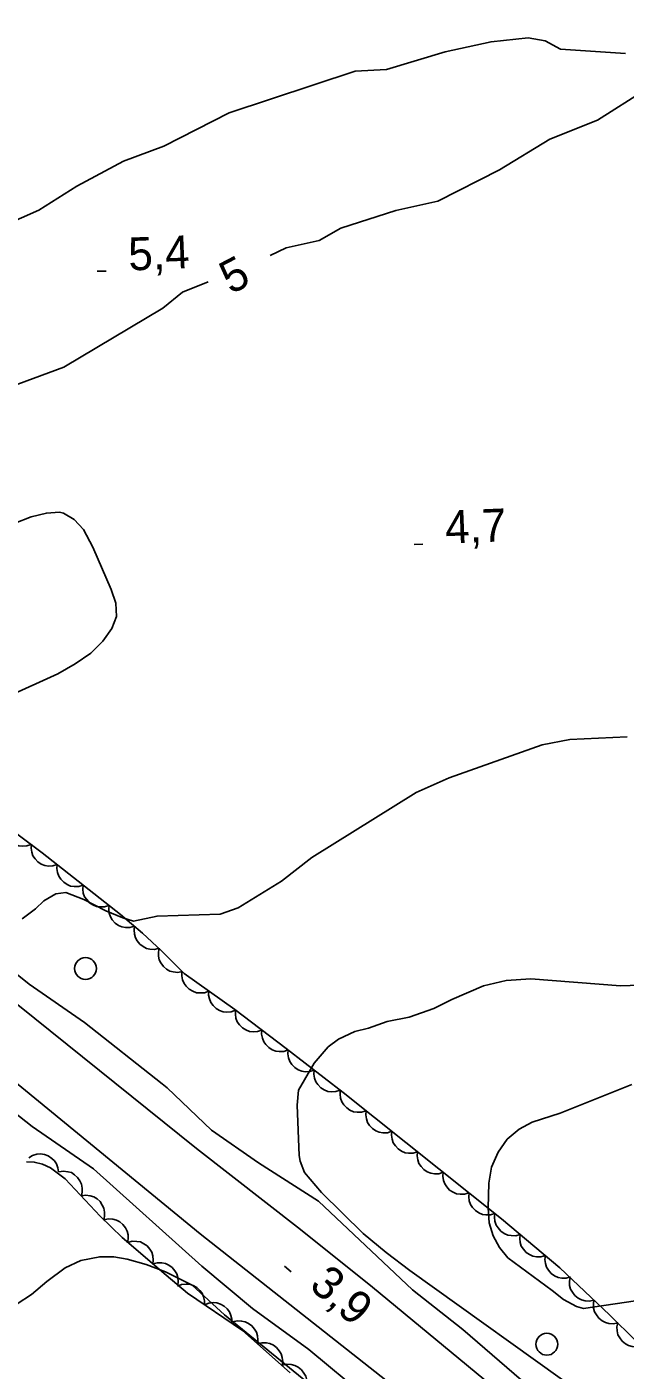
# Model space of a CAD drawing. Extents: x 336540 to 340074, y 5572036 to 5573747.
# Drawn here: x 337681.5 to 337736, y 5572772.1 to 5572894.5 of the extents above; entities that cross this region are included whole.
import ezdxf

# ---------------------------------------------------------------- set-up
doc = ezdxf.new("R2010")
doc.units = 0
for name, color, linetype in [('Niveau 1', 7, 'Continuous'), ('Niveau 19', 7, 'Continuous'), ('Niveau 2', 7, 'Continuous'), ('Niveau 3', 7, 'Continuous'), ('Niveau 36', 7, 'Continuous'), ('Niveau 4', 7, 'Continuous'), ('Niveau 44', 7, 'Continuous')]:
    doc.layers.add(name, color=color, linetype=linetype)

msp = doc.modelspace()

# ---------------------------------------------------------------- linework, layer by layer
at = {"layer": 'Niveau 1'}
for points in [[(337675.98, 5572874.9), (337682.62, 5572877.81), (337686.06, 5572880.01), (337690.32, 5572882.28), (337693.99, 5572883.65), (337699.93, 5572886.67), (337711.41, 5572890.48), (337714.27, 5572890.62), (337719.61, 5572892.25), (337723.79, 5572893.15), (337727.15, 5572893.51), (337728.7, 5572893.24), (337730.1, 5572892.47), (337736.03, 5572892.08)], [(337737.88, 5572888.79), (337733.47, 5572886), (337729.15, 5572884.28), (337724.56, 5572881.49), (337718.95, 5572878.64), (337715.11, 5572877.78), (337710.11, 5572876.16), (337708.12, 5572875.04), (337705.13, 5572874.37), (337703.68, 5572873.67)], [(337698.04, 5572871.27), (337695.7, 5572870.33), (337693.9, 5572868.87), (337684.87, 5572863.51), (337677.88, 5572860.94)], [(337736.92, 5572778.46), (337732.2, 5572777.75), (337731.56, 5572777.93), (337730.37, 5572778.57), (337729.36, 5572779.4), (337725.32, 5572782.38), (337724.55, 5572783.31), (337723.98, 5572784.38), (337723.61, 5572785.56), (337723.53, 5572786.92), (337723.58, 5572789.18), (337723.82, 5572790.62), (337724.43, 5572792), (337725.26, 5572793.17), (337726.33, 5572794.09), (337727.52, 5572794.72), (337730.09, 5572795.55), (337736.61, 5572798.15)]]:
    msp.add_lwpolyline(points, dxfattribs=at)
at = {"layer": 'Niveau 19'}
for points in [[(337747.9, 5572743.42), (337733.2, 5572755.24), (337714.79, 5572770.78), (337697.31, 5572784.55), (337659.54, 5572815.53), (337637.6, 5572833.7), (337630.44, 5572839.48), (337615.68, 5572851.12), (337606.88, 5572858.17), (337562.43, 5572894.51)], [(337585.33, 5572882.89), (337594.24, 5572875.34), (337602.7, 5572868.36), (337610.46, 5572862.12), (337627.18, 5572849.32), (337671.83, 5572812.51), (337696.95, 5572792.34), (337706.42, 5572784.95), (337712.98, 5572779.69), (337742.53, 5572755.28)]]:
    msp.add_lwpolyline(points, dxfattribs=at)
at = {"layer": 'Niveau 2'}
for points in [[(337680.35, 5572849.26), (337681.92, 5572849.87), (337683.3, 5572850.22), (337684.48, 5572850.29), (337684.84, 5572850.22), (337685.82, 5572849.63), (337686.67, 5572848.71), (337687.54, 5572847.12), (337689.19, 5572843.24), (337689.61, 5572842.01), (337689.67, 5572840.78), (337689.26, 5572839.71), (337688.45, 5572838.56), (337687.35, 5572837.46), (337685.91, 5572836.47), (337684.35, 5572835.57), (337679.73, 5572833.49)], [(337681.08, 5572813.24), (337682.32, 5572814.15), (337683.06, 5572814.88), (337684.17, 5572815.54), (337685.07, 5572815.64), (337686.71, 5572815), (337688.7, 5572813.99), (337690.27, 5572813.33), (337691.23, 5572813.05), (337693.38, 5572813.5), (337699.11, 5572813.68), (337700.75, 5572814.26), (337704.71, 5572816.68), (337707.46, 5572818.85), (337716.97, 5572824.77), (337719.96, 5572826.11), (337728.43, 5572829.1), (337730.95, 5572829.58), (337736.17, 5572829.84)], [(337740.01, 5572807.29), (337735.56, 5572807.14), (337727.39, 5572807.8), (337725.17, 5572807.65), (337723.09, 5572807.15), (337720.2, 5572805.9), (337718.57, 5572805.07), (337716.33, 5572804.3), (337714.32, 5572803.89), (337712.63, 5572803.29), (337711.39, 5572802.98), (337709.9, 5572802.3), (337708.95, 5572801.58), (337707.67, 5572800.11), (337706.26, 5572797.64), (337706.12, 5572796.27), (337706.3, 5572791.69), (337706.39, 5572791.17), (337706.81, 5572790.15), (337708.36, 5572788.31), (337712.14, 5572784.59), (337714.23, 5572782.86), (337716.39, 5572781.22), (337732.33, 5572769.81)], [(337707.41, 5572770.74), (337699.51, 5572777.17), (337696.57, 5572779.87), (337694.13, 5572781.09), (337692.39, 5572781.76), (337690.66, 5572782.24), (337689.44, 5572782.46), (337688.15, 5572782.47), (337686.44, 5572782.12), (337685.01, 5572781.45), (337683.35, 5572780.21), (337681.95, 5572779.03), (337680.64, 5572778.19)]]:
    msp.add_lwpolyline(points, dxfattribs=at)
at = {"layer": 'Niveau 3'}
for p, q in [((337687.93, 5572872.24), (337688.73, 5572872.26)), ((337716.77, 5572847.36), (337717.58, 5572847.39)), ((337704.98, 5572781.6), (337705.59, 5572781.08))]:
    msp.add_line(p, q, dxfattribs=at)
at = {"layer": 'Niveau 36'}
for centre in [(337686.86, 5572808.73), (337728.86, 5572774.5)]:
    msp.add_circle(centre, 1, dxfattribs=at)
at = {"layer": 'Niveau 4'}
for points in [[(337581.38, 5572889.43), (337592.52, 5572879.92), (337597.05, 5572876.33), (337601.9, 5572872.72), (337604.6, 5572870.54), (337609.27, 5572866.45), (337613.37, 5572862.68), (337615.91, 5572860.57), (337624.81, 5572853.45), (337633.16, 5572846.53), (337638.87, 5572842.03), (337643.3, 5572838.72), (337649.78, 5572834.11), (337653.45, 5572831.32), (337655.58, 5572829.56), (337666.32, 5572820.01), (337674.23, 5572813.3), (337681.73, 5572807.3), (337686.77, 5572803.82), (337693.83, 5572798.21)], [(337587.92, 5572869.67), (337590.52, 5572867.82), (337595.97, 5572864.2), (337609.79, 5572853.86), (337616.42, 5572848.76), (337622.03, 5572843.92), (337633.87, 5572834.25), (337644.17, 5572825.44), (337649.15, 5572820.98), (337662.3, 5572809.95), (337669.6, 5572804.24), (337675.77, 5572799.23), (337681.99, 5572794.33), (337687.59, 5572790.49), (337697.46, 5572781.61), (337702.07, 5572777.76), (337707.2, 5572774.01), (337712.37, 5572769.72), (337716.28, 5572765.83), (337730.4, 5572754.32), (337734.94, 5572750.56), (337739.53, 5572746.61)], [(337693.83, 5572798.21), (337694.3, 5572797.86), (337698.32, 5572794), (337702.62, 5572791.02), (337708.08, 5572787.53), (337716.63, 5572779.47), (337721.2, 5572775.84), (337729.89, 5572768.34), (337739.09, 5572761.24)]]:
    msp.add_lwpolyline(points, dxfattribs=at)
at = {"layer": 'Niveau 44'}
for points in [[(337681.91, 5572820.02), (337681.51, 5572819.89), (337681.11, 5572819.87), (337680.78, 5572819.9), (337680.45, 5572820.03), (337680.14, 5572820.22), (337679.87, 5572820.5), (337679.67, 5572820.76), (337679.55, 5572821.09), (337679.48, 5572821.45), (337679.5, 5572821.81)], [(337739.35, 5572772.45), (337734.57, 5572777.18), (337730.04, 5572781.47), (337724.74, 5572785.92), (337710.33, 5572797.42), (337705.12, 5572801.45), (337700.44, 5572804.98), (337695.84, 5572808.27), (337693.79, 5572810.35), (337692.04, 5572811.95), (337690.03, 5572813.64), (337682.91, 5572819.28), (337680.35, 5572821.18)], [(337684.28, 5572818.19), (337683.88, 5572818.07), (337683.48, 5572818.06), (337683.15, 5572818.1), (337682.83, 5572818.24), (337682.52, 5572818.45), (337682.26, 5572818.73), (337682.07, 5572819), (337681.96, 5572819.33), (337681.9, 5572819.7), (337681.93, 5572820.06)], [(337686.63, 5572816.33), (337686.24, 5572816.2), (337685.83, 5572816.2), (337685.5, 5572816.24), (337685.18, 5572816.38), (337684.87, 5572816.58), (337684.61, 5572816.87), (337684.42, 5572817.13), (337684.31, 5572817.47), (337684.26, 5572817.83), (337684.28, 5572818.19)], [(337688.99, 5572814.47), (337688.59, 5572814.34), (337688.18, 5572814.34), (337687.85, 5572814.38), (337687.53, 5572814.52), (337687.22, 5572814.72), (337686.97, 5572815.01), (337686.77, 5572815.27), (337686.66, 5572815.6), (337686.61, 5572815.97), (337686.63, 5572816.33)], [(337691.31, 5572812.57), (337690.9, 5572812.45), (337690.5, 5572812.46), (337690.17, 5572812.51), (337689.85, 5572812.66), (337689.55, 5572812.87), (337689.3, 5572813.16), (337689.12, 5572813.43), (337689.02, 5572813.77), (337688.97, 5572814.14), (337689.01, 5572814.5)], [(337693.55, 5572810.57), (337693.14, 5572810.47), (337692.73, 5572810.5), (337692.41, 5572810.56), (337692.1, 5572810.73), (337691.81, 5572810.95), (337691.57, 5572811.25), (337691.4, 5572811.53), (337691.31, 5572811.87), (337691.28, 5572812.24), (337691.33, 5572812.6)], [(337695.66, 5572808.45), (337695.25, 5572808.37), (337694.85, 5572808.42), (337694.53, 5572808.5), (337694.23, 5572808.68), (337693.95, 5572808.92), (337693.73, 5572809.23), (337693.57, 5572809.52), (337693.5, 5572809.86), (337693.49, 5572810.23), (337693.56, 5572810.58)], [(337698.08, 5572806.67), (337697.69, 5572806.52), (337697.28, 5572806.5), (337696.95, 5572806.52), (337696.62, 5572806.65), (337696.3, 5572806.84), (337696.03, 5572807.11), (337695.83, 5572807.36), (337695.7, 5572807.69), (337695.63, 5572808.06), (337695.64, 5572808.42)], [(337700.52, 5572804.93), (337700.13, 5572804.78), (337699.72, 5572804.76), (337699.39, 5572804.78), (337699.06, 5572804.9), (337698.74, 5572805.09), (337698.47, 5572805.36), (337698.27, 5572805.62), (337698.14, 5572805.95), (337698.07, 5572806.31), (337698.08, 5572806.67)], [(337702.91, 5572803.12), (337702.52, 5572802.98), (337702.11, 5572802.97), (337701.78, 5572803), (337701.45, 5572803.13), (337701.14, 5572803.33), (337700.88, 5572803.61), (337700.68, 5572803.87), (337700.56, 5572804.2), (337700.5, 5572804.56), (337700.52, 5572804.92)], [(337705.31, 5572801.31), (337704.91, 5572801.17), (337704.5, 5572801.16), (337704.18, 5572801.19), (337703.85, 5572801.33), (337703.54, 5572801.52), (337703.27, 5572801.8), (337703.08, 5572802.06), (337702.96, 5572802.39), (337702.89, 5572802.76), (337702.91, 5572803.12)], [(337707.68, 5572799.47), (337707.28, 5572799.34), (337706.87, 5572799.33), (337706.55, 5572799.37), (337706.22, 5572799.51), (337705.91, 5572799.71), (337705.65, 5572799.99), (337705.46, 5572800.25), (337705.34, 5572800.58), (337705.28, 5572800.95), (337705.3, 5572801.31)], [(337710.05, 5572797.64), (337709.65, 5572797.51), (337709.25, 5572797.5), (337708.92, 5572797.53), (337708.59, 5572797.67), (337708.28, 5572797.87), (337708.02, 5572798.15), (337707.83, 5572798.41), (337707.72, 5572798.75), (337707.65, 5572799.11), (337707.68, 5572799.47)], [(337712.4, 5572795.77), (337712, 5572795.65), (337711.59, 5572795.64), (337711.26, 5572795.68), (337710.94, 5572795.83), (337710.64, 5572796.03), (337710.38, 5572796.32), (337710.19, 5572796.58), (337710.08, 5572796.92), (337710.03, 5572797.28), (337710.05, 5572797.64)], [(337714.74, 5572793.9), (337714.34, 5572793.77), (337713.94, 5572793.77), (337713.61, 5572793.81), (337713.29, 5572793.95), (337712.98, 5572794.16), (337712.72, 5572794.44), (337712.53, 5572794.71), (337712.43, 5572795.04), (337712.37, 5572795.41), (337712.4, 5572795.77)], [(337717.09, 5572792.03), (337716.69, 5572791.9), (337716.28, 5572791.9), (337715.95, 5572791.94), (337715.63, 5572792.08), (337715.33, 5572792.29), (337715.07, 5572792.57), (337714.88, 5572792.84), (337714.77, 5572793.17), (337714.71, 5572793.54), (337714.74, 5572793.9)], [(337681.5, 5572791.13), (337682.19, 5572791.1), (337682.95, 5572790.9), (337683.68, 5572790.56), (337685.02, 5572789.58), (337688.18, 5572786.18), (337690.19, 5572784.23), (337694.19, 5572780.78), (337696.14, 5572779.16), (337701.14, 5572775.75), (337705.5, 5572771.9)], [(337681.69, 5572791.49), (337682.04, 5572791.7), (337682.44, 5572791.8), (337682.77, 5572791.84), (337683.11, 5572791.78), (337683.46, 5572791.65), (337683.78, 5572791.43), (337684.02, 5572791.22), (337684.21, 5572790.92), (337684.35, 5572790.58), (337684.41, 5572790.22)], [(337719.43, 5572790.16), (337719.03, 5572790.03), (337718.63, 5572790.03), (337718.3, 5572790.07), (337717.98, 5572790.21), (337717.67, 5572790.42), (337717.41, 5572790.7), (337717.22, 5572790.97), (337717.11, 5572791.3), (337717.06, 5572791.67), (337717.09, 5572792.03)], [(337684.43, 5572790.21), (337684.85, 5572790.27), (337685.25, 5572790.22), (337685.57, 5572790.13), (337685.87, 5572789.94), (337686.14, 5572789.69), (337686.35, 5572789.37), (337686.5, 5572789.08), (337686.56, 5572788.73), (337686.56, 5572788.36), (337686.48, 5572788.01)], [(337721.78, 5572788.28), (337721.38, 5572788.16), (337720.97, 5572788.16), (337720.64, 5572788.2), (337720.32, 5572788.34), (337720.01, 5572788.54), (337719.76, 5572788.83), (337719.57, 5572789.1), (337719.46, 5572789.43), (337719.4, 5572789.8), (337719.43, 5572790.16)], [(337686.48, 5572788.01), (337686.89, 5572788.08), (337687.29, 5572788.02), (337687.61, 5572787.93), (337687.91, 5572787.74), (337688.18, 5572787.49), (337688.39, 5572787.17), (337688.54, 5572786.88), (337688.6, 5572786.54), (337688.6, 5572786.17), (337688.52, 5572785.81)], [(337724.12, 5572786.41), (337723.72, 5572786.29), (337723.32, 5572786.29), (337722.99, 5572786.33), (337722.67, 5572786.47), (337722.36, 5572786.67), (337722.1, 5572786.96), (337721.91, 5572787.22), (337721.8, 5572787.56), (337721.75, 5572787.93), (337721.78, 5572788.28)], [(337726.43, 5572784.5), (337726.03, 5572784.38), (337725.62, 5572784.39), (337725.3, 5572784.44), (337724.98, 5572784.59), (337724.68, 5572784.8), (337724.43, 5572785.1), (337724.24, 5572785.36), (337724.14, 5572785.7), (337724.1, 5572786.07), (337724.13, 5572786.43)], [(337688.54, 5572785.83), (337688.95, 5572785.92), (337689.35, 5572785.88), (337689.67, 5572785.81), (337689.98, 5572785.64), (337690.27, 5572785.4), (337690.49, 5572785.09), (337690.66, 5572784.81), (337690.73, 5572784.47), (337690.75, 5572784.1), (337690.69, 5572783.74)], [(337690.72, 5572783.77), (337691.12, 5572783.88), (337691.53, 5572783.87), (337691.85, 5572783.82), (337692.17, 5572783.66), (337692.47, 5572783.45), (337692.71, 5572783.15), (337692.89, 5572782.88), (337692.99, 5572782.54), (337693.03, 5572782.17), (337692.99, 5572781.81)], [(337728.73, 5572782.57), (337728.33, 5572782.46), (337727.92, 5572782.46), (337727.59, 5572782.51), (337727.28, 5572782.66), (337726.97, 5572782.87), (337726.73, 5572783.17), (337726.54, 5572783.44), (337726.44, 5572783.77), (337726.4, 5572784.14), (337726.43, 5572784.5)], [(337731.03, 5572780.64), (337730.63, 5572780.53), (337730.22, 5572780.53), (337729.89, 5572780.58), (337729.57, 5572780.73), (337729.27, 5572780.95), (337729.02, 5572781.24), (337728.84, 5572781.51), (337728.74, 5572781.84), (337728.69, 5572782.21), (337728.73, 5572782.57)], [(337692.99, 5572781.81), (337693.39, 5572781.92), (337693.8, 5572781.91), (337694.13, 5572781.86), (337694.44, 5572781.7), (337694.74, 5572781.49), (337694.99, 5572781.19), (337695.17, 5572780.92), (337695.26, 5572780.58), (337695.3, 5572780.21), (337695.26, 5572779.86)], [(337695.22, 5572779.79), (337695.6, 5572779.94), (337696.01, 5572779.98), (337696.34, 5572779.96), (337696.67, 5572779.84), (337696.99, 5572779.66), (337697.27, 5572779.4), (337697.48, 5572779.15), (337697.61, 5572778.82), (337697.69, 5572778.46), (337697.69, 5572778.1)], [(337733.15, 5572778.52), (337732.75, 5572778.43), (337732.34, 5572778.46), (337732.02, 5572778.53), (337731.71, 5572778.7), (337731.42, 5572778.93), (337731.19, 5572779.24), (337731.02, 5572779.52), (337730.94, 5572779.86), (337730.92, 5572780.23), (337730.98, 5572780.58)], [(337697.69, 5572778.1), (337698.08, 5572778.25), (337698.49, 5572778.29), (337698.82, 5572778.27), (337699.15, 5572778.15), (337699.47, 5572777.97), (337699.75, 5572777.71), (337699.96, 5572777.46), (337700.09, 5572777.13), (337700.17, 5572776.77), (337700.17, 5572776.41)], [(337735.33, 5572776.46), (337734.92, 5572776.37), (337734.52, 5572776.4), (337734.2, 5572776.47), (337733.89, 5572776.64), (337733.6, 5572776.87), (337733.37, 5572777.17), (337733.2, 5572777.45), (337733.12, 5572777.8), (337733.1, 5572778.17), (337733.15, 5572778.52)], [(337700.26, 5572776.53), (337700.67, 5572776.63), (337701.07, 5572776.61), (337701.4, 5572776.55), (337701.71, 5572776.4), (337702.01, 5572776.18), (337702.25, 5572775.88), (337702.43, 5572775.61), (337702.52, 5572775.27), (337702.56, 5572774.9), (337702.51, 5572774.54)], [(337737.45, 5572774.33), (337737.04, 5572774.25), (337736.63, 5572774.29), (337736.31, 5572774.37), (337736.01, 5572774.54), (337735.72, 5572774.78), (337735.5, 5572775.09), (337735.34, 5572775.37), (337735.27, 5572775.72), (337735.25, 5572776.09), (337735.32, 5572776.44)], [(337702.51, 5572774.54), (337702.92, 5572774.64), (337703.32, 5572774.63), (337703.65, 5572774.57), (337703.96, 5572774.41), (337704.26, 5572774.19), (337704.5, 5572773.89), (337704.68, 5572773.62), (337704.77, 5572773.28), (337704.81, 5572772.91), (337704.76, 5572772.55)], [(337704.78, 5572772.58), (337705.19, 5572772.67), (337705.59, 5572772.64), (337705.92, 5572772.57), (337706.23, 5572772.4), (337706.52, 5572772.17), (337706.75, 5572771.87), (337706.92, 5572771.59), (337707, 5572771.24), (337707.02, 5572770.88), (337706.96, 5572770.52)]]:
    msp.add_lwpolyline(points, dxfattribs=at)

# ---------------------------------------------------------------- texts
at = {"layer": 'Niveau 1'}
msp.add_text('5', height=3, rotation=27.5797, dxfattribs=at).set_placement((337700.09, 5572870.1))
at = {"layer": 'Niveau 3'}
for s, rotation, p in [('5,4    ', 2.2763, (337690.81, 5572872.31)), ('4,7    ', 2.2763, (337719.65, 5572847.43)), ('3,9    ', 318.977, (337707.12, 5572779.69))]:
    msp.add_text(s, height=3, rotation=rotation, dxfattribs=at).set_placement(p)

doc.saveas('drawing.dxf')
